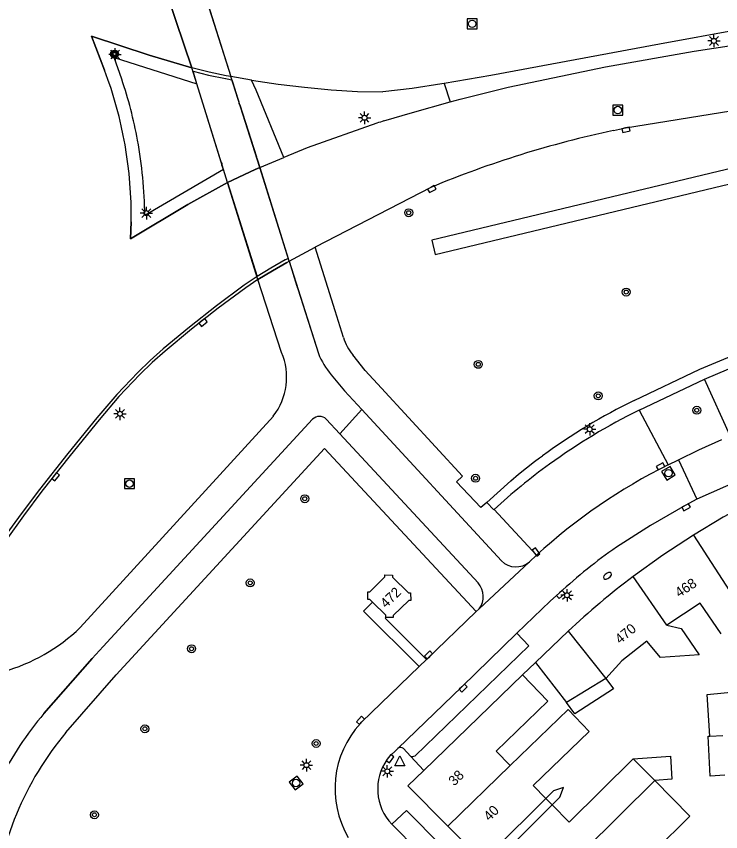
# Model space of a CAD drawing. Extents: x 132573 to 132944, y 398226 to 398676.
# Drawn here: x 132790.1 to 132860.9, y 398502.5 to 398584.5 of the extents above; entities that cross this region are included whole.
import ezdxf

# ---------------------------------------------------------------- set-up
doc = ezdxf.new("R2010")
doc.units = 0
for name, color, linetype in [('gg-afsc-erfafscheiding', 7, 'Continuous'), ('gg-anno-huisnummerreeks BGT', 7, 'Continuous'), ('gg-bbg-bijgebouw', 7, 'Continuous'), ('gg-bbg-gedigitaliseerde bebouwing', 7, 'Continuous'), ('gg-bbg-gedigitaliseerde bebouwing onder overbouw', 7, 'Continuous'), ('gg-bbg-gedigitaliseerde bijgebouw', 7, 'Continuous'), ('gg-bbg-gedigitaliseerde overbouw', 7, 'Continuous'), ('gg-bbg-hoofdgebouw', 7, 'Continuous'), ('gg-bbg-luifel en loopbrug', 7, 'Continuous'), ('gg-bbg-tussenscheiding', 7, 'Continuous'), ('gg-knt-verharding', 7, 'Continuous'), ('gg-knt-verharding nz', 7, 'Continuous'), ('gt-grn-groengrens', 7, 'Continuous'), ('gt-symb-boom', 7, 'Continuous'), ('gt-symb-brandkraan', 7, 'Continuous'), ('gt-symb-kolk', 7, 'Continuous'), ('gt-symb-lichtmast', 7, 'Continuous'), ('gt-symb-portaalmast', 7, 'Continuous'), ('gt-symb-rioolschacht', 7, 'Continuous'), ('gt-symb-waterafsluiter', 7, 'Continuous'), ('ir-asfa-asfalt arcering', 7, 'Continuous'), ('ir-asfa-asfalt rood', 7, 'Continuous')]:
    doc.layers.add(name, color=color, linetype=linetype)

msp = doc.modelspace()

# ---------------------------------------------------------------- linework, layer by layer
at = {"layer": 'gg-afsc-erfafscheiding'}
msp.add_lwpolyline([(132843.982, 398505.172), (132844.763, 398505.947), (132845.132, 398506.918), (132844.115, 398506.599), (132843.335, 398505.824)], dxfattribs=at)
at = {"layer": 'gg-bbg-bijgebouw'}
for p, q in [((132845.585, 398522.636), (132842.32, 398519.481)), ((132842.32, 398519.481), (132845.416, 398515.452))]:
    msp.add_line(p, q, dxfattribs=at)
at = {"layer": 'gg-bbg-gedigitaliseerde bebouwing'}
for p, q in [((132852.116, 398509.812), (132854.288, 398507.624)), ((132857.824, 398504.05), (132854.288, 398507.624)), ((132857.824, 398504.05), (132851.47, 398497.765))]:
    msp.add_line(p, q, dxfattribs=at)
for points in [[(132860.969, 398522.391), (132858.839, 398525.456), (132855.502, 398523.243)], [(132855.502, 398523.243), (132856.929, 398522.923), (132858.746, 398520.252), (132854.863, 398519.983), (132853.497, 398521.629), (132850.979, 398519.663), (132849.38, 398517.892)], [(132841, 398518.251), (132843.555, 398515.615), (132838.361, 398510.578), (132839.775, 398509.119)], [(132839.775, 398509.119), (132845.589, 398514.753), (132847.708, 398512.566), (132842.081, 398507.12), (132843.335, 398505.824)], [(132843.982, 398505.172), (132845.698, 398503.443), (132852.116, 398509.812)]]:
    msp.add_lwpolyline(points, dxfattribs=at)
at = {"layer": 'gg-bbg-gedigitaliseerde bebouwing onder overbouw'}
for p, q in [((132836.992, 398499.53), (132843.335, 398505.824)), ((132837.639, 398498.878), (132843.982, 398505.172))]:
    msp.add_line(p, q, dxfattribs=at)
at = {"layer": 'gg-bbg-gedigitaliseerde bijgebouw'}
for p, q in [((132849.38, 398517.892), (132845.416, 398515.452)), ((132859.837, 398512.077), (132861.118, 398512.163))]:
    msp.add_line(p, q, dxfattribs=at)
msp.add_lwpolyline([(132859.837, 398512.077), (132859.565, 398516.283), (132862.643, 398516.565), (132864.298, 398514.792)], dxfattribs=at)
at = {"layer": 'gg-bbg-gedigitaliseerde overbouw'}
msp.add_line((132843.335, 398505.824), (132843.982, 398505.172), dxfattribs=at)
at = {"layer": 'gg-bbg-hoofdgebouw'}
for p, q in [((132841, 398518.251), (132831.092, 398508.644)), ((132833.506, 398503.044), (132836.992, 398499.53))]:
    msp.add_line(p, q, dxfattribs=at)
for points in [[(132863.872, 398535.546), (132861.179, 398534.096), (132858.174, 398532.307)], [(132858.174, 398532.307), (132855.095, 398530.288), (132852.111, 398528.133)], [(132825.932, 398525.569), (132825.67, 398525.831), (132825.46, 398525.831), (132825.46, 398526.591), (132825.67, 398526.591), (132827.16, 398528.091), (132827.16, 398528.301), (132827.94, 398528.281), (132827.94, 398528.071), (132829.53, 398526.491), (132829.74, 398526.491), (132829.77, 398525.721), (132829.56, 398525.711), (132828.01, 398524.211), (132828.01, 398524.001), (132827.25, 398524.031)], [(132827.25, 398524.031), (132827.26, 398524.241), (132825.932, 398525.569)], [(132833.506, 398503.044), (132829.49, 398507.091), (132831.092, 398508.644)]]:
    msp.add_lwpolyline(points, dxfattribs=at)
msp.add_arc((132901.264, 398463.156), 81.474, 127.10659, 133.10983, dxfattribs=at)
at = {"layer": 'gg-bbg-luifel en loopbrug'}
msp.add_line((132846.251, 398514.324), (132845.416, 398515.452), dxfattribs=at)
for points in [[(132849.38, 398517.892), (132850.148, 398516.84), (132846.251, 398514.324)], [(132861.347, 398508.149), (132859.851, 398508.075), (132859.654, 398512.068), (132859.837, 398512.077)], [(132852.116, 398509.812), (132855.864, 398510.08), (132856.01, 398507.752), (132854.288, 398507.624)]]:
    msp.add_lwpolyline(points, dxfattribs=at)
at = {"layer": 'gg-bbg-tussenscheiding'}
for p, q in [((132858.174, 398532.307), (132862.911, 398524.963)), ((132855.502, 398523.243), (132852.111, 398528.133)), ((132845.585, 398522.636), (132849.38, 398517.892)), ((132839.775, 398509.119), (132833.506, 398503.044)), ((132841.529, 398494.958), (132854.288, 398507.624))]:
    msp.add_line(p, q, dxfattribs=at)
at = {"layer": 'gg-knt-verharding'}
for p, q in [((132864.406, 398583.453), (132854.757, 398581.671)), ((132808.27, 398577.705), (132807.78, 398579.291)), ((132811.673, 398578.431), (132811.224, 398578.51)), ((132813.774, 398578.063), (132811.673, 398578.431)), ((132814.6, 398569.261), (132811.673, 398578.431)), ((132810.932, 398569.078), (132808.27, 398577.705)), ((132833.116, 398577.729), (132833.719, 398575.867)), ((132814.6, 398569.261), (132817.022, 398570.272)), ((132810.932, 398569.078), (132803.039, 398564.458)), ((132811.34, 398567.758), (132810.932, 398569.078)), ((132814.12, 398569.061), (132811.34, 398567.758)), ((132814.12, 398569.061), (132814.6, 398569.261)), ((132831.789, 398567.278), (132820.145, 398561.27)), ((132817.532, 398559.841), (132820.145, 398561.27)), ((132822.17, 398554.857), (132820.145, 398561.27)), ((132817.31, 398559.72), (132817.532, 398559.841)), ((132817.532, 398559.841), (132820.491, 398550.571)), ((132816.789, 398550.678), (132814.41, 398558.002)), ((132823.006, 398552.178), (132822.17, 398554.857)), ((132859.304, 398548), (132868.18, 398551.756)), ((132861.856, 398542.29), (132859.304, 398548)), ((132796.539, 398523.008), (132815.955, 398544.272)), ((132824.847, 398544.927), (132838.881, 398529.719)), ((132852.71, 398544.867), (132855.624, 398539.369)), ((132822.638, 398542.494), (132821.281, 398543.96)), ((132836.53, 398527.488), (132822.638, 398542.494)), ((132800.148, 398518.249), (132821.101, 398541.005)), ((132821.101, 398541.005), (132836.348, 398524.607)), ((132855.624, 398539.369), (132856.665, 398539.883)), ((132856.665, 398539.883), (132858.535, 398535.906)), ((132862.897, 398537.875), (132858.535, 398535.906)), ((132838.11, 398534.831), (132837.406, 398535.591)), ((132838.159, 398534.895), (132838.11, 398534.831)), ((132842.396, 398530.27), (132838.159, 398534.895)), ((132842.396, 398530.27), (132841.687, 398529.63)), ((132841.687, 398529.63), (132836.643, 398524.879)), ((132836.348, 398524.607), (132831.358, 398519.79)), ((132836.348, 398524.607), (132836.643, 398524.879)), ((132841.623, 398521.182), (132840.423, 398522.43)), ((132841.623, 398521.182), (132830.197, 398510.113)), ((132792.898, 398514.364), (132797.739, 398519.891)), ((132830.629, 398519.092), (132831.358, 398519.79)), ((132841, 398518.251), (132842.32, 398519.481)), ((132795.113, 398512.455), (132800.148, 398518.249)), ((132829.034, 398510.829), (132829.734, 398510.058)), ((132829.734, 398510.058), (132831.092, 398508.644)), ((132852.879, 398477.985), (132827.875, 398503.225))]:
    msp.add_line(p, q, dxfattribs=at)
for points in [[(132798.991, 398579.06), (132797.695, 398582.474), (132803.46, 398580.581), (132807.78, 398579.291)], [(132833.719, 398575.867), (132834.722, 398576.148), (132839.572, 398577.354), (132849.354, 398579.386), (132858.236, 398580.967), (132864.634, 398581.957)], [(132854.757, 398581.671), (132837.817, 398578.542), (132833.116, 398577.729)], [(132800.717, 398578.159), (132799.947, 398580.336), (132808.27, 398577.705)], [(132811.224, 398578.51), (132809.494, 398578.866), (132807.78, 398579.291)], [(132813.774, 398578.063), (132816.45, 398577.667), (132819.099, 398577.349), (132821.755, 398577.09), (132824.418, 398576.93), (132826.952, 398576.873)], [(132817.022, 398570.272), (132814.246, 398577.038), (132813.774, 398578.063)], [(132833.116, 398577.729), (132832.884, 398577.689), (132829.924, 398577.21), (132826.952, 398576.873)], [(132850.137, 398572.989), (132851.351, 398573.263), (132872.519, 398576.694), (132875.328, 398577.144)], [(132827.073, 398573.96), (132829.936, 398574.808), (132833.719, 398575.867)], [(132826.36, 398573.741), (132819.37, 398571.251), (132817.022, 398570.272)], [(132811.34, 398567.758), (132807.36, 398565.541), (132801.612, 398562.102), (132801.672, 398563.795)], [(132817.31, 398559.72), (132815.855, 398558.89), (132814.41, 398558.002)], [(132814.41, 398558.002), (132813.19, 398557.181), (132810.42, 398555.136), (132807.72, 398553), (132805.071, 398550.8), (132803.779, 398549.661), (132802.542, 398548.463), (132800.438, 398546.23), (132798.437, 398543.904), (132795.544, 398540.327), (132792.7, 398536.71), (132790.857, 398534.259), (132789.059, 398531.775), (132787.312, 398529.255), (132786.355, 398527.786)], [(132826.816, 398547.093), (132825.19, 398548.862), (132823.941, 398550.436)], [(132821.773, 398548.44), (132823.099, 398546.821), (132824.847, 398544.927)], [(132837.406, 398535.591), (132836.813, 398535.069), (132834.379, 398537.658), (132834.97, 398538.223), (132826.816, 398547.093)], [(132819.907, 398543.955), (132798.847, 398521.113), (132797.739, 398519.891)], [(132856.665, 398539.883), (132858.71, 398540.892), (132861.045, 398541.93)], [(132858.535, 398535.906), (132857.354, 398535.282), (132853.859, 398533.255), (132850.439, 398531.103)], [(132844.716, 398526.483), (132843.781, 398525.675), (132840.423, 398522.43)], [(132830.629, 398519.092), (132825.025, 398524.654), (132825.932, 398525.569)], [(132827.25, 398524.031), (132827.18, 398523.945), (132831.358, 398519.79)], [(132824.707, 398513.363), (132824.865, 398513.531), (132830.629, 398519.092)], [(132828.466, 398510.846), (132827.533, 398509.933), (132827.406, 398509.759)]]:
    msp.add_lwpolyline(points, dxfattribs=at)
for centre, radius, start, end in [((132760.438, 398564.421), 41.239, 359.1302, 20.79239), ((132759.092, 398564.098), 43.935, 10.39946, 18.66491), ((132843.563, 398519.005), 57.376, 106.70207, 107.44691), ((132871.623, 398471.631), 103.61, 101.9684, 112.61016), ((132758.655, 398563.982), 44.386, 0.61458, 10.44533), ((132827.438, 398553.435), 4.606, 195.83222, 220.61619), ((132810.839, 398548.195), 6.447, 322.51495, 22.64977), ((132827.312, 398553.223), 7.318, 201.24814, 220.81372), ((132820.597, 398543.257), 0.982, 45.78622, 134.63078), ((132880.129, 398489.256), 62.003, 116.2453, 125.98646), ((132880.127, 398489.258), 62, 125.98621, 132.60162), ((132881.577, 398486.676), 54.253, 125.02608, 132.79964), ((132840.33, 398531.125), 2.019, 224.1376, 312.22903), ((132834.978, 398526.114), 2.073, 323.44534, 41.51471), ((132783.799, 398536.268), 18.388, 285.72504, 313.85379), ((132818.767, 398492.492), 33.876, 139.78652, 153.45237), ((132831.859, 398506.802), 9.706, 137.469, 210.2954), ((132819.131, 398492.312), 31.346, 140.01365, 175.24514), ((132828.741, 398510.553), 0.402, 43.31652, 133.25482), ((132831.549, 398506.773), 5.107, 144.21702, 223.9941), ((132829.908, 398510.573), 0.543, 251.36718, 302.18171)]:
    msp.add_arc(centre, radius, start, end, dxfattribs=at)
at = {"layer": 'gg-knt-verharding nz'}
for p, q in [((132807.78, 398579.291), (132804.517, 398588.97)), ((132808.782, 398587.62), (132811.673, 398578.431)), ((132817.532, 398559.841), (132814.6, 398569.261)), ((132814.41, 398558.002), (132811.34, 398567.758)), ((132840.423, 398522.43), (132834.886, 398517.059)), ((132828.466, 398510.846), (132834.886, 398517.059))]:
    msp.add_line(p, q, dxfattribs=at)
msp.add_lwpolyline([(132852.879, 398477.985), (132854.282, 398479.381), (132829.326, 398504.618), (132827.875, 398503.225)], dxfattribs=at)
msp.add_arc((132881.512, 398487.569), 57.909, 116.55422, 132.49076, dxfattribs=at)
at = {"layer": 'gt-grn-groengrens'}
for p, q in [((132858.832, 398548.994), (132867.751, 398552.769)), ((132852.224, 398545.854), (132858.832, 398548.994)), ((132852.71, 398544.867), (132859.304, 398548))]:
    msp.add_line(p, q, dxfattribs=at)
for points in [[(132831.875, 398561.969), (132832.225, 398560.51), (132868.409, 398569.194), (132868.059, 398570.653), (132831.875, 398561.969)], [(132837.406, 398535.591), (132839.813, 398537.769), (132840.591, 398538.419), (132842.196, 398539.707), (132842.697, 398540.072), (132843.025, 398540.29)]]:
    msp.add_lwpolyline(points, dxfattribs=at)
msp.add_arc((132880.285, 398489.074), 63.336, 116.29897, 126.03619, dxfattribs=at)
at = {"layer": 'gt-symb-boom'}
for centre, radius in [((132829.563, 398564.731), 0.4), ((132829.563, 398564.731), 0.2), ((132851.418, 398556.75), 0.4), ((132851.418, 398556.75), 0.2), ((132836.557, 398549.479), 0.4), ((132836.557, 398549.479), 0.2), ((132848.609, 398546.308), 0.4), ((132848.609, 398546.308), 0.2), ((132858.519, 398544.861), 0.4), ((132858.519, 398544.861), 0.2), ((132836.278, 398538.021), 0.4), ((132836.278, 398538.021), 0.2), ((132819.118, 398535.964), 0.4), ((132819.118, 398535.964), 0.2), ((132813.627, 398527.501), 0.4), ((132813.627, 398527.501), 0.2), ((132807.738, 398520.875), 0.4), ((132807.738, 398520.875), 0.2), ((132803.043, 398512.821), 0.4), ((132803.043, 398512.821), 0.2), ((132820.26, 398511.345), 0.4), ((132820.26, 398511.345), 0.2), ((132797.978, 398504.171), 0.4), ((132797.978, 398504.171), 0.2)]:
    msp.add_circle(centre, radius, dxfattribs=at)
at = {"layer": 'gt-symb-brandkraan'}
for centre, radius, start, end in [((132849.345, 398528.074), 0.206, 143.29107, 288.15721), ((132851.585, 398526.404), 3, 142.61618, 143.29107), ((132849.946, 398527.656), 0.938, 108.83212, 142.61618), ((132848.474, 398530.73), 3, 288.15721, 288.83211), ((132849.14, 398528.778), 0.938, 288.83211, 322.6162), ((132850.612, 398525.704), 3, 108.15722, 108.83212), ((132849.741, 398528.36), 0.206, 323.29109, 108.15722), ((132847.501, 398530.03), 3, 322.6162, 323.29109)]:
    msp.add_arc(centre, radius, start, end, dxfattribs=at)
at = {"layer": 'gt-symb-kolk'}
for points in [[(132851.351, 398573.263), (132850.985, 398573.181), (132851.073, 398572.79), (132851.805, 398572.955), (132851.717, 398573.345), (132851.351, 398573.263)], [(132831.789, 398567.278), (132831.456, 398567.106), (132831.639, 398566.751), (132832.306, 398567.094), (132832.122, 398567.45), (132831.789, 398567.278)], [(132808.765, 398553.845), (132808.472, 398553.611), (132808.722, 398553.298), (132809.308, 398553.767), (132809.058, 398554.079), (132808.765, 398553.845)], [(132854.963, 398539.034), (132855.297, 398539.205), (132855.114, 398539.561), (132854.447, 398539.219), (132854.629, 398538.863), (132854.963, 398539.034)], [(132793.921, 398538.291), (132793.69, 398537.996), (132794.005, 398537.749), (132794.467, 398538.34), (132794.152, 398538.586), (132793.921, 398538.291)], [(132857.354, 398535.282), (132857.024, 398535.104), (132857.214, 398534.752), (132857.874, 398535.108), (132857.684, 398535.46), (132857.354, 398535.282)], [(132842.206, 398530.477), (132842.43, 398530.176), (132842.751, 398530.415), (132842.303, 398531.017), (132841.982, 398530.778), (132842.206, 398530.477)], [(132844.716, 398526.483), (132844.432, 398526.238), (132844.694, 398525.935), (132845.261, 398526.425), (132845, 398526.728), (132844.716, 398526.483)], [(132831.694, 398520.111), (132831.965, 398520.37), (132831.689, 398520.659), (132831.147, 398520.141), (132831.423, 398519.852), (132831.694, 398520.111)], [(132834.886, 398517.059), (132834.617, 398516.798), (132834.895, 398516.511), (132835.434, 398517.033), (132835.155, 398517.32), (132834.886, 398517.059)], [(132824.865, 398513.531), (132825.121, 398513.805), (132824.829, 398514.078), (132824.317, 398513.531), (132824.609, 398513.257), (132824.865, 398513.531)], [(132827.533, 398509.933), (132827.312, 398509.63), (132827.635, 398509.394), (132828.077, 398510), (132827.754, 398510.236), (132827.533, 398509.933)]]:
    msp.add_lwpolyline(points, dxfattribs=at)
at = {"layer": 'gt-symb-lichtmast'}
for p, q in [((132859.99, 398582.005), (132859.615, 398582.005)), ((132860.063, 398582.182), (132859.798, 398582.447)), ((132860.24, 398582.255), (132860.24, 398582.63)), ((132860.417, 398582.182), (132860.682, 398582.447)), ((132860.49, 398582.005), (132860.865, 398582.005)), ((132799.871, 398580.818), (132799.606, 398581.083)), ((132800.048, 398580.891), (132800.048, 398581.266)), ((132800.225, 398580.818), (132800.49, 398581.083)), ((132860.063, 398581.828), (132859.798, 398581.563)), ((132860.24, 398581.755), (132860.24, 398581.38)), ((132860.682, 398581.563), (132860.417, 398581.828)), ((132799.798, 398580.641), (132799.423, 398580.641)), ((132799.871, 398580.464), (132799.606, 398580.199)), ((132800.048, 398580.391), (132800.048, 398580.016)), ((132800.49, 398580.199), (132800.225, 398580.464)), ((132800.298, 398580.641), (132800.673, 398580.641)), ((132824.95, 398574.45), (132824.685, 398574.715)), ((132825.127, 398574.523), (132825.127, 398574.898)), ((132825.304, 398574.45), (132825.569, 398574.715)), ((132824.877, 398574.273), (132824.502, 398574.273)), ((132824.95, 398574.096), (132824.685, 398573.831)), ((132825.127, 398574.023), (132825.127, 398573.648)), ((132825.569, 398573.831), (132825.304, 398574.096)), ((132825.377, 398574.273), (132825.752, 398574.273)), ((132802.941, 398564.686), (132802.566, 398564.686)), ((132803.014, 398564.863), (132802.749, 398565.128)), ((132803.191, 398564.936), (132803.191, 398565.311)), ((132803.368, 398564.863), (132803.633, 398565.128)), ((132803.441, 398564.686), (132803.816, 398564.686)), ((132803.014, 398564.509), (132802.749, 398564.244)), ((132803.191, 398564.436), (132803.191, 398564.061)), ((132803.633, 398564.244), (132803.368, 398564.509)), ((132800.543, 398544.756), (132800.543, 398545.131)), ((132800.293, 398544.506), (132799.918, 398544.506)), ((132800.366, 398544.683), (132800.101, 398544.948)), ((132800.366, 398544.329), (132800.101, 398544.064)), ((132800.543, 398544.256), (132800.543, 398543.881)), ((132800.72, 398544.683), (132800.985, 398544.948)), ((132800.985, 398544.064), (132800.72, 398544.329)), ((132800.793, 398544.506), (132801.168, 398544.506)), ((132847.574, 398543.127), (132847.309, 398543.392)), ((132847.751, 398543.2), (132847.751, 398543.575)), ((132847.928, 398543.127), (132848.193, 398543.392)), ((132847.501, 398542.95), (132847.126, 398542.95)), ((132847.574, 398542.773), (132847.309, 398542.508)), ((132847.751, 398542.7), (132847.751, 398542.325)), ((132848.193, 398542.508), (132847.928, 398542.773)), ((132848.001, 398542.95), (132848.376, 398542.95)), ((132845.222, 398526.254), (132844.847, 398526.254)), ((132845.295, 398526.431), (132845.03, 398526.696)), ((132845.472, 398526.504), (132845.472, 398526.879)), ((132845.914, 398526.696), (132845.649, 398526.431)), ((132845.722, 398526.254), (132846.097, 398526.254)), ((132845.295, 398526.077), (132845.03, 398525.812)), ((132845.472, 398526.004), (132845.472, 398525.629)), ((132845.649, 398526.077), (132845.914, 398525.812)), ((132819.28, 398509.417), (132819.28, 398509.792)), ((132819.03, 398509.167), (132818.655, 398509.167)), ((132819.103, 398509.344), (132818.838, 398509.609)), ((132819.103, 398508.99), (132818.838, 398508.725)), ((132819.28, 398508.917), (132819.28, 398508.542)), ((132819.457, 398509.344), (132819.722, 398509.609)), ((132819.722, 398508.725), (132819.457, 398508.99)), ((132819.53, 398509.167), (132819.905, 398509.167)), ((132827.233, 398508.726), (132826.968, 398508.991)), ((132827.41, 398508.799), (132827.41, 398509.174)), ((132827.587, 398508.726), (132827.852, 398508.991)), ((132827.16, 398508.549), (132826.785, 398508.549)), ((132827.233, 398508.372), (132826.968, 398508.107)), ((132827.41, 398508.299), (132827.41, 398507.924)), ((132827.852, 398508.107), (132827.587, 398508.372)), ((132827.66, 398508.549), (132828.035, 398508.549))]:
    msp.add_line(p, q, dxfattribs=at)
for centre in [(132860.24, 398582.005), (132800.048, 398580.641), (132825.127, 398574.273), (132803.191, 398564.686), (132800.543, 398544.506), (132847.751, 398542.95), (132845.472, 398526.254), (132819.28, 398509.167), (132827.41, 398508.549)]:
    msp.add_circle(centre, 0.25, dxfattribs=at)
at = {"layer": 'gt-symb-portaalmast'}
for radius in [0.4, 0.33, 0.27, 0.21, 0.15]:
    msp.add_circle((132799.998, 398580.687), radius, dxfattribs=at)
at = {"layer": 'gt-symb-rioolschacht'}
for points in [[(132835.438, 398583.226), (132836.438, 398583.226), (132836.438, 398584.226), (132835.438, 398584.226)], [(132850.081, 398574.556), (132851.081, 398574.556), (132851.081, 398575.556), (132850.081, 398575.556)], [(132854.98, 398538.693), (132855.502, 398537.841), (132856.354, 398538.363), (132855.832, 398539.215)], [(132800.997, 398536.975), (132801.997, 398536.975), (132801.997, 398537.975), (132800.997, 398537.975)], [(132818.342, 398508.07), (132817.544, 398507.468), (132818.146, 398506.67), (132818.944, 398507.272)]]:
    msp.add_lwpolyline(points, close=True, dxfattribs=at)
for centre in [(132835.938, 398583.726), (132850.581, 398575.056), (132855.667, 398538.528), (132801.497, 398537.475), (132818.244, 398507.37)]:
    msp.add_circle(centre, 0.375, dxfattribs=at)
at = {"layer": 'gt-symb-waterafsluiter'}
for p, q in [((132828.158, 398509.097), (132828.658, 398510.097)), ((132828.658, 398510.097), (132829.158, 398509.097)), ((132829.158, 398509.097), (132828.158, 398509.097))]:
    msp.add_line(p, q, dxfattribs=at)
at = {"layer": 'ir-asfa-asfalt arcering'}
for points in [[(132788.013, 398596.897), (132790.609, 398595.29), (132793.274, 398593.802), (132796.001, 398592.428), (132796.184, 398592.345), (132796.182, 398592.34), (132796.862, 398592.024), (132796.867, 398592.035), (132798.781, 398591.166), (132801.609, 398590.017), (132804.517, 398588.97), (132807.78, 398579.291), (132803.46, 398580.581), (132797.695, 398582.474), (132798.991, 398579.06)], [(132801.672, 398563.795), (132801.612, 398562.102), (132807.36, 398565.541), (132811.34, 398567.758), (132814.317, 398558.297), (132814.253, 398558.258), (132814.243, 398558.251), (132813.017, 398557.426), (132810.238, 398555.374), (132807.531, 398553.233), (132804.876, 398551.028), (132803.575, 398549.881), (132802.328, 398548.674), (132800.215, 398546.431), (132798.207, 398544.096), (132795.309, 398540.514), (132792.462, 398536.893), (132790.616, 398534.437), (132788.814, 398531.948), (132787.063, 398529.422), (132786.105, 398527.952)]]:
    msp.add_lwpolyline(points, dxfattribs=at)
for points in [[(132811.673, 398578.431), (132811.224, 398578.51), (132809.494, 398578.866), (132807.78, 398579.291), (132804.517, 398588.97), (132804.75, 398588.891), (132808.286, 398587.739), (132808.782, 398587.62)], [(132817.166, 398559.983), (132817.161, 398559.981), (132815.702, 398559.148), (132814.317, 398558.297), (132811.34, 398567.758), (132814.12, 398569.061), (132814.6, 398569.261), (132817.441, 398560.133), (132817.388, 398560.104)]]:
    msp.add_lwpolyline(points, close=True, dxfattribs=at)
msp.add_arc((132760.438, 398564.421), 41.239, 359.1302, 20.79239, dxfattribs=at)
at = {"layer": 'ir-asfa-asfalt rood'}
for p, q in [((132812.128, 398577.005), (132812.488, 398575.878)), ((132812.582, 398575.583), (132814.251, 398570.355)), ((132818.411, 398557.087), (132820.491, 398550.571)), ((132796.539, 398523.008), (132815.955, 398544.272))]:
    msp.add_line(p, q, dxfattribs=at)
for points in [[(132810.706, 398569.811), (132808.27, 398577.705), (132807.883, 398578.956), (132809.428, 398578.573), (132811.164, 398578.216), (132811.172, 398578.215), (132811.621, 398578.135), (132811.776, 398578.108), (132812.109, 398577.065)], [(132814.33, 398570.107), (132814.6, 398569.261), (132814.12, 398569.061), (132811.34, 398567.758), (132810.932, 398569.078), (132810.795, 398569.522)], [(132816.789, 398550.678), (132814.41, 398558.002), (132815.855, 398558.89), (132817.31, 398559.72), (132817.532, 398559.841), (132818.332, 398557.335)], [(132821.773, 398548.44), (132823.099, 398546.821), (132824.847, 398544.927), (132822.638, 398542.494), (132821.281, 398543.96)], [(132819.907, 398543.955), (132798.847, 398521.113), (132797.739, 398519.891), (132792.898, 398514.364)]]:
    msp.add_lwpolyline(points, dxfattribs=at)
for centre, radius, start, end in [((132812.355, 398577.11), 0.25, 190.48298, 204.92246), ((132812.722, 398575.79), 0.25, 159.42562, 235.97983), ((132810.56, 398569.608), 0.25, 339.97127, 54.32564), ((132814.494, 398570.296), 0.25, 166.45823, 228.94721), ((132818.575, 398557.276), 0.25, 166.40915, 228.9972), ((132810.839, 398548.195), 6.447, 322.51495, 22.64977), ((132827.312, 398553.223), 7.318, 201.24814, 220.81372), ((132820.597, 398543.257), 0.982, 45.78622, 134.63078), ((132783.799, 398536.268), 18.388, 285.72504, 313.85379), ((132818.767, 398492.492), 33.876, 139.78652, 153.45237)]:
    msp.add_arc(centre, radius, start, end, dxfattribs=at)

# ---------------------------------------------------------------- texts
at = {"layer": 'gg-anno-huisnummerreeks BGT'}
for s, rotation, p in [('468', 33.2, (132856.741, 398525.988)), ('472', 44.1, (132827.28, 398524.895)), ('470', 40.1, (132850.81, 398521.3)), ('38', 44.8, (132834.148, 398507.017)), ('40', 44.8, (132837.668, 398503.473))]:
    msp.add_text(s, height=1, rotation=rotation, dxfattribs=at).set_placement(p)

doc.saveas('drawing.dxf')
